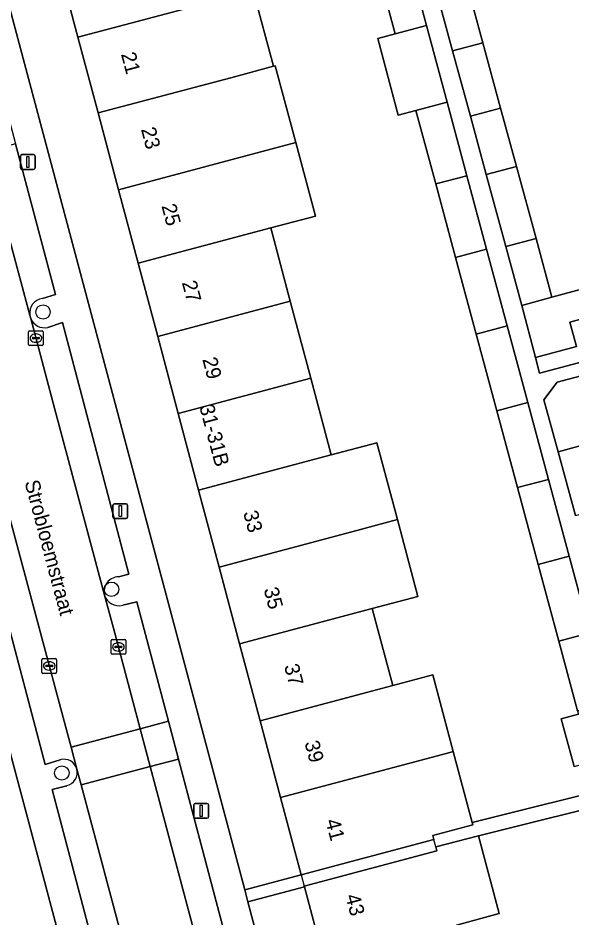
# Model space of a CAD drawing. Extents: x 162542 to 163147, y 380779 to 381521.
# Drawn here: x 162765.3 to 162802.8, y 380919.2 to 380980.2 of the extents above; entities that cross this region are included whole.
import ezdxf

# ---------------------------------------------------------------- set-up
doc = ezdxf.new("R2010")
doc.units = 0
for name, color, linetype in [('IMGEO_Boom', 7, 'Continuous'), ('IMGEO_Erf', 7, 'Continuous'), ('IMGEO_Kolk', 7, 'Continuous'), ('IMGEO_Lichtmast', 7, 'Continuous'), ('IMGEO_Openbare_ruimte_label', 7, 'Continuous'), ('IMGEO_Pand', 7, 'Continuous'), ('IMGEO_Pand_nummerreeks', 7, 'Continuous'), ('IMGEO_Pand_overbouw', 7, 'Continuous'), ('IMGEO_Parkeervlak_open', 7, 'Continuous'), ('IMGEO_Rijbaan_lokaal_open', 7, 'Continuous'), ('IMGEO_Voetpad_open', 7, 'Continuous')]:
    doc.layers.add(name, color=color, linetype=linetype)

msp = doc.modelspace()

# ---------------------------------------------------------------- linework, layer by layer
at = {"layer": 'IMGEO_Boom'}
for centre in [(162766.947, 380960.27), (162771.589, 380941.474), (162768.223, 380929.016)]:
    msp.add_circle(centre, 0.489, dxfattribs=at)
at = {"layer": 'IMGEO_Erf'}
for points in [[(162776.104, 380953.39), (162774.717, 380958.599), (162773.391, 380963.577), (162772.064, 380968.558), (162770.678, 380973.763), (162769.31, 380978.899), (162767.898, 380984.203), (162767.79, 380984.608), (162763.955, 380983.585), (162780.617, 380921.086), (162784.437, 380922.105), (162783.04, 380927.349), (162781.653, 380932.556), (162780.266, 380937.765), (162778.879, 380942.973), (162777.492, 380948.181)], [(162751.467, 380980.135), (162747.619, 380979.111), (162747.702, 380978.798), (162749.067, 380973.666), (162750.432, 380968.535), (162751.797, 380963.403), (162753.162, 380958.272), (162754.527, 380953.141), (162755.892, 380948.009), (162757.257, 380942.877), (162758.623, 380937.745), (162759.988, 380932.613), (162761.352, 380927.483), (162762.717, 380922.351), (162764.079, 380917.227), (162767.943, 380918.262)], [(162787.389, 380911.023), (162785.994, 380916.261), (162784.652, 380921.296), (162780.832, 380920.278), (162787.754, 380894.316), (162788.858, 380889.82), (162787.979, 380889.585), (162787.726, 380889.027), (162790.444, 380878.831), (162792.701, 380879.433), (162791.368, 380884.436), (162789.872, 380890.054), (162791.407, 380890.462), (162790.439, 380894.095), (162791.801, 380894.457), (162791.485, 380895.645), (162790.126, 380900.745), (162788.743, 380905.938)]]:
    msp.add_lwpolyline(points, close=True, dxfattribs=at)
for points in [[(162803.166, 380933.225), (162801.894, 380937.951), (162800.493, 380943.157), (162799.092, 380948.361), (162797.692, 380953.565), (162796.291, 380958.771), (162794.89, 380963.976), (162793.551, 380968.951), (162792.211, 380973.928), (162791.013, 380973.608), (162789.626, 380978.814), (162790.811, 380979.13), (162789.431, 380984.26)], [(162795.55, 380982.944), (162796.75, 380978.521), (162797.95, 380974.098), (162799.023, 380970.143), (162800.35, 380965.253), (162801.428, 380961.277), (162804.268, 380962.047)], [(162781.192, 380982.065), (162782.56, 380976.93), (162782.685, 380976.963), (162784.072, 380971.758), (162785.399, 380966.777), (162782.376, 380965.972), (162783.702, 380960.994), (162785.089, 380955.785), (162786.477, 380950.576), (162789.569, 380951.4), (162790.956, 380946.192), (162792.343, 380940.984), (162789.251, 380940.16), (162790.638, 380934.951), (162793.348, 380935.673), (162794.735, 380930.466), (162796.013, 380925.666), (162806.622, 380928.295)], [(162808.637, 380961.215), (162802.639, 380959.589), (162803.085, 380957.942), (162800.308, 380957.189), (162800.588, 380956.117), (162814.194, 380959.734)], [(162802.928, 380929.454), (162802.058, 380932.686), (162803.227, 380933)], [(162806.857, 380927.348), (162796.44, 380924.766), (162797.847, 380919.483), (162794.967, 380918.7), (162796.43, 380913.206), (162797.685, 380908.496), (162799.067, 380903.307), (162800.42, 380898.227), (162801.843, 380892.883), (162801.926, 380892.571), (162803.223, 380887.695), (162800.276, 380886.911), (162800.948, 380884.389), (162801.506, 380882.293), (162801.634, 380881.813), (162815.673, 380885.555)]]:
    msp.add_lwpolyline(points, dxfattribs=at)
at = {"layer": 'IMGEO_Kolk'}
for p, q in [((162765.967, 380958.074), (162765.967, 380958.926)), ((162766.042, 380959), (162766.894, 380959)), ((162766.455, 380958.78), (162766.48, 380958.78)), ((162766.968, 380958.926), (162766.968, 380958.074)), ((162766.226, 380958.494), (162766.226, 380958.506)), ((162766.664, 380958.457), (162766.266, 380958.457)), ((162766.269, 380958.543), (162766.667, 380958.543)), ((162766.478, 380958.22), (162766.453, 380958.22)), ((162766.71, 380958.506), (162766.71, 380958.494)), ((162766.894, 380958), (162766.042, 380958)), ((162771.629, 380938.062), (162772.481, 380938.062)), ((162771.554, 380937.136), (162771.554, 380937.988)), ((162771.813, 380937.556), (162771.813, 380937.568)), ((162772.251, 380937.519), (162771.853, 380937.519)), ((162771.856, 380937.605), (162772.254, 380937.605)), ((162772.042, 380937.842), (162772.067, 380937.842)), ((162772.297, 380937.568), (162772.297, 380937.556)), ((162772.555, 380937.988), (162772.555, 380937.136)), ((162772.481, 380937.062), (162771.629, 380937.062)), ((162772.065, 380937.282), (162772.04, 380937.282)), ((162766.869, 380935.846), (162766.869, 380936.698)), ((162766.944, 380936.772), (162767.796, 380936.772)), ((162767.128, 380936.266), (162767.128, 380936.278)), ((162767.566, 380936.229), (162767.168, 380936.229)), ((162767.171, 380936.315), (162767.569, 380936.315)), ((162767.357, 380936.552), (162767.382, 380936.552)), ((162767.612, 380936.278), (162767.612, 380936.266)), ((162767.87, 380936.698), (162767.87, 380935.846)), ((162767.796, 380935.772), (162766.944, 380935.772)), ((162767.38, 380935.992), (162767.355, 380935.992))]:
    msp.add_line(p, q, dxfattribs=at)
for points in [[(162765.967, 380958.074), (162765.967, 380958.926)], [(162766.042, 380959), (162766.894, 380959)], [(162766.968, 380958.926), (162766.968, 380958.074)], [(162766.894, 380958), (162766.042, 380958)], [(162771.629, 380938.062), (162772.481, 380938.062)], [(162771.554, 380937.136), (162771.554, 380937.988)], [(162772.555, 380937.988), (162772.555, 380937.136)], [(162772.481, 380937.062), (162771.629, 380937.062)], [(162766.869, 380935.846), (162766.869, 380936.698)], [(162766.944, 380936.772), (162767.796, 380936.772)], [(162767.87, 380936.698), (162767.87, 380935.846)], [(162767.796, 380935.772), (162766.944, 380935.772)]]:
    msp.add_lwpolyline(points, dxfattribs=at)
for centre, radius, start, end in [((162766.044, 380958.924), 0.0765, 91.55205, 178.44795), ((162766.044, 380958.924), 0.0765, 91.55205, 178.44795), ((162766.892, 380958.924), 0.0765, 1.55205, 88.44795), ((162766.892, 380958.924), 0.0765, 1.55205, 88.44795), ((162766.266, 380958.503), 0.0403, 85.87752, 175.75265), ((162766.263, 380958.493), 0.0366, 178.93798, 274.71019), ((162766.667, 380958.5), 0.043, 264.86636, 352.45326), ((162766.671, 380958.505), 0.0386, 1.73085, 96.63898), ((162766.044, 380958.076), 0.0765, 181.55205, 268.44795), ((162766.044, 380958.076), 0.0765, 181.55205, 268.44795), ((162766.892, 380958.076), 0.0765, 271.55205, 358.44795), ((162766.892, 380958.076), 0.0765, 271.55205, 358.44795), ((162771.631, 380937.986), 0.0765, 91.55205, 178.44795), ((162771.631, 380937.986), 0.0765, 91.55205, 178.44795), ((162772.479, 380937.986), 0.0765, 1.55205, 88.44795), ((162772.479, 380937.986), 0.0765, 1.55205, 88.44795), ((162771.853, 380937.565), 0.0403, 85.87752, 175.75265), ((162771.85, 380937.555), 0.0366, 178.93798, 274.71019), ((162772.254, 380937.562), 0.043, 264.86636, 352.45326), ((162772.258, 380937.567), 0.0386, 1.73085, 96.63898), ((162771.631, 380937.138), 0.0765, 181.55205, 268.44795), ((162771.631, 380937.138), 0.0765, 181.55205, 268.44795), ((162772.479, 380937.138), 0.0765, 271.55205, 358.44795), ((162772.479, 380937.138), 0.0765, 271.55205, 358.44795), ((162766.946, 380936.696), 0.0765, 91.55205, 178.44795), ((162766.946, 380936.696), 0.0765, 91.55205, 178.44795), ((162767.168, 380936.275), 0.0403, 85.87752, 175.75265), ((162767.165, 380936.265), 0.0366, 178.93798, 274.71019), ((162767.569, 380936.272), 0.043, 264.86636, 352.45326), ((162767.573, 380936.277), 0.0386, 1.73085, 96.63898), ((162767.794, 380936.696), 0.0765, 1.55205, 88.44795), ((162767.794, 380936.696), 0.0765, 1.55205, 88.44795), ((162766.946, 380935.848), 0.0765, 181.55205, 268.44795), ((162766.946, 380935.848), 0.0765, 181.55205, 268.44795), ((162767.794, 380935.848), 0.0765, 271.55205, 358.44795), ((162767.794, 380935.848), 0.0765, 271.55205, 358.44795)]:
    msp.add_arc(centre, radius, start, end, dxfattribs=at)
for centre, major_axis, ratio, start_param, end_param in [((162766.454, 380958.5), (-0.387, 0.002), 0.722429, 4.712389, 7.853982), ((162766.479, 380958.5), (-0.39, 0.002), 0.717154, 1.570796, 4.712389), ((162772.041, 380937.562), (-0.387, 0.002), 0.722429, 4.712389, 7.853982), ((162772.066, 380937.562), (-0.39, 0.002), 0.717154, 1.570796, 4.712389), ((162767.356, 380936.272), (-0.387, 0.002), 0.722429, 4.712389, 7.853982), ((162767.381, 380936.272), (-0.39, 0.002), 0.717154, 1.570796, 4.712389)]:
    msp.add_ellipse(centre, major_axis=major_axis, ratio=ratio, start_param=start_param, end_param=end_param, dxfattribs=at)
at = {"layer": 'IMGEO_Lichtmast'}
for p, q in [((162765.423, 380970.042), (162765.423, 380970.842)), ((162765.423, 380970.842), (162765.423, 380970.042)), ((162765.523, 380970.942), (162766.313, 380970.942)), ((162766.313, 380970.942), (162765.523, 380970.942)), ((162766.413, 380970.842), (162766.413, 380970.042)), ((162766.413, 380970.042), (162766.413, 380970.842)), ((162766.313, 380969.942), (162765.523, 380969.942)), ((162765.523, 380969.942), (162766.313, 380969.942)), ((162771.787, 380947.27), (162772.577, 380947.27)), ((162772.577, 380947.27), (162771.787, 380947.27)), ((162771.687, 380946.37), (162771.687, 380947.17)), ((162771.687, 380947.17), (162771.687, 380946.37)), ((162772.677, 380947.17), (162772.677, 380946.37)), ((162772.677, 380946.37), (162772.677, 380947.17)), ((162772.577, 380946.27), (162771.787, 380946.27)), ((162771.787, 380946.27), (162772.577, 380946.27)), ((162777.166, 380926.051), (162777.166, 380926.851)), ((162777.166, 380926.851), (162777.166, 380926.051)), ((162777.266, 380926.951), (162778.056, 380926.951)), ((162778.056, 380926.951), (162777.266, 380926.951)), ((162778.156, 380926.851), (162778.156, 380926.051)), ((162778.156, 380926.051), (162778.156, 380926.851)), ((162778.056, 380925.951), (162777.266, 380925.951)), ((162777.266, 380925.951), (162778.056, 380925.951))]:
    msp.add_line(p, q, dxfattribs=at)
for points in [[(162765.843, 380970.817), (162765.993, 380970.817), (162765.993, 380970.067), (162765.843, 380970.067), (162765.843, 380970.817)], [(162772.107, 380947.145), (162772.257, 380947.145), (162772.257, 380946.395), (162772.107, 380946.395), (162772.107, 380947.145)], [(162777.586, 380926.826), (162777.736, 380926.826), (162777.736, 380926.076), (162777.586, 380926.076), (162777.586, 380926.826)]]:
    msp.add_lwpolyline(points, dxfattribs=at)
for centre, start, end in [((162765.523, 380970.842), 90, 180), ((162765.523, 380970.842), 90, 180), ((162766.313, 380970.842), 0, 90), ((162766.313, 380970.842), 360, 90), ((162765.523, 380970.042), 180, 270), ((162765.523, 380970.042), 180, 270), ((162766.313, 380970.042), 270, 0), ((162766.313, 380970.042), 270, 0), ((162771.787, 380947.17), 90, 180), ((162771.787, 380947.17), 90, 180), ((162772.577, 380947.17), 0, 90), ((162772.577, 380947.17), 360, 90), ((162771.787, 380946.37), 180, 270), ((162771.787, 380946.37), 180, 270), ((162772.577, 380946.37), 270, 0), ((162772.577, 380946.37), 270, 0), ((162777.266, 380926.851), 90, 180), ((162777.266, 380926.851), 90, 180), ((162778.056, 380926.851), 0, 90), ((162778.056, 380926.851), 360, 90), ((162777.266, 380926.051), 180, 270), ((162777.266, 380926.051), 180, 270), ((162778.056, 380926.051), 270, 0), ((162778.056, 380926.051), 270, 0)]:
    msp.add_arc(centre, 0.1, start, end, dxfattribs=at)
at = {"layer": 'IMGEO_Pand'}
for points in [[(162779.767, 380987.412), (162779.654, 380987.837), (162776.758, 380987.065), (162776.416, 380986.974), (162776.539, 380986.511), (162771.439, 380985.144), (162767.898, 380984.203), (162769.31, 380978.899), (162781.192, 380982.065)], [(162789.431, 380984.26), (162790.811, 380979.13), (162792.92, 380979.692), (162791.54, 380984.822)], [(162795.55, 380982.944), (162793.499, 380982.396), (162794.699, 380977.973), (162796.75, 380978.521)], [(162781.192, 380982.065), (162769.31, 380978.899), (162770.678, 380973.763), (162779.663, 380976.158), (162782.56, 380976.93)], [(162792.92, 380979.692), (162790.811, 380979.13), (162789.626, 380978.814), (162791.013, 380973.608), (162792.211, 380973.928), (162794.318, 380974.49)], [(162796.75, 380978.521), (162794.699, 380977.973), (162795.899, 380973.55), (162797.95, 380974.098)], [(162782.685, 380976.963), (162782.56, 380976.93), (162779.663, 380976.158), (162770.678, 380973.763), (162772.064, 380968.558), (162784.072, 380971.758)], [(162792.211, 380973.928), (162793.551, 380968.951), (162795.657, 380969.512), (162794.318, 380974.49)], [(162797.95, 380974.098), (162795.899, 380973.55), (162796.974, 380969.587), (162799.023, 380970.143)], [(162782.376, 380965.972), (162785.399, 380966.777), (162784.072, 380971.758), (162772.064, 380968.558), (162773.391, 380963.577)], [(162799.023, 380970.143), (162796.974, 380969.587), (162798.299, 380964.704), (162800.35, 380965.253)], [(162794.89, 380963.976), (162796.994, 380964.537), (162795.657, 380969.512), (162793.551, 380968.951)], [(162774.717, 380958.599), (162783.702, 380960.994), (162782.376, 380965.972), (162773.391, 380963.577)], [(162800.35, 380965.253), (162798.299, 380964.704), (162799.38, 380960.722), (162801.428, 380961.277)], [(162796.994, 380964.537), (162794.89, 380963.976), (162796.291, 380958.771), (162798.394, 380959.331)], [(162808.637, 380961.215), (162808.128, 380963.094), (162804.268, 380962.047), (162801.428, 380961.277), (162799.38, 380960.722), (162800.308, 380957.189), (162803.085, 380957.942), (162802.639, 380959.589)], [(162774.717, 380958.599), (162776.104, 380953.39), (162785.089, 380955.785), (162783.702, 380960.994)], [(162797.692, 380953.565), (162799.794, 380954.126), (162798.394, 380959.331), (162796.291, 380958.771)], [(162805.701, 380956.553), (162801.771, 380955.512), (162800.881, 380954.316), (162801.843, 380950.786), (162806.711, 380952.113), (162806.876, 380952.157)], [(162785.089, 380955.785), (162776.104, 380953.39), (162777.492, 380948.181), (162786.477, 380950.576)], [(162801.193, 380948.921), (162799.794, 380954.126), (162797.692, 380953.565), (162799.092, 380948.361)], [(162806.711, 380952.113), (162801.843, 380950.786), (162803.02, 380946.469), (162807.872, 380947.765)], [(162786.477, 380950.576), (162777.492, 380948.181), (162778.879, 380942.973), (162787.864, 380945.368), (162790.956, 380946.192), (162789.569, 380951.4)], [(162801.193, 380948.921), (162799.092, 380948.361), (162800.493, 380943.157), (162802.592, 380943.716)], [(162787.864, 380945.368), (162778.879, 380942.973), (162780.266, 380937.765), (162789.251, 380940.16), (162792.343, 380940.984), (162790.956, 380946.192)], [(162801.894, 380937.951), (162803.992, 380938.511), (162802.592, 380943.716), (162800.493, 380943.157)], [(162780.266, 380937.765), (162781.653, 380932.556), (162790.638, 380934.951), (162789.251, 380940.16)], [(162801.894, 380937.951), (162803.166, 380933.225), (162805.261, 380933.789), (162803.992, 380938.511)], [(162793.348, 380935.673), (162790.638, 380934.951), (162781.653, 380932.556), (162783.04, 380927.349), (162794.354, 380930.365), (162794.735, 380930.466)], [(162805.261, 380933.789), (162803.166, 380933.225), (162803.227, 380933), (162802.058, 380932.686), (162802.928, 380929.454), (162806.122, 380930.314)], [(162796.013, 380925.666), (162794.735, 380930.466), (162794.354, 380930.365), (162783.04, 380927.349), (162784.437, 380922.105), (162793.422, 380924.5), (162793.35, 380924.768), (162796.06, 380925.49)], [(162796.44, 380924.766), (162793.556, 380923.998), (162793.626, 380923.737), (162784.64, 380921.342), (162784.652, 380921.296), (162785.994, 380916.261), (162794.967, 380918.7), (162797.847, 380919.483)]]:
    msp.add_lwpolyline(points, close=True, dxfattribs=at)
at = {"layer": 'IMGEO_Pand_overbouw'}
msp.add_lwpolyline([(162793.626, 380923.737), (162793.556, 380923.998), (162793.422, 380924.5), (162784.437, 380922.105), (162784.64, 380921.342)], close=True, dxfattribs=at)
at = {"layer": 'IMGEO_Parkeervlak_open'}
for points in [[(162766.904, 380961.192), (162767.792, 380961.461), (162765.084, 380971.665), (162763.108, 380971.14), (162764.244, 380966.819), (162766.059, 380960.054)], [(162766.115, 380959.838), (162767.646, 380954.085), (162771.115, 380941.082)], [(162772.068, 380942.321), (162772.766, 380942.488), (162768.266, 380959.557), (162767.263, 380959.225)], [(162769.244, 380929.276), (162768.845, 380930.769), (162768.149, 380933.373), (162764.006, 380948.824), (162763.748, 380949.807)], [(162763.22, 380948.728), (162762.116, 380948.396), (162767.103, 380929.588), (162768.105, 380929.907)], [(162771.115, 380941.082), (162771.712, 380938.843), (162773.532, 380932.015), (162775.443, 380932.523), (162773.303, 380940.622), (162772.351, 380940.392)], [(162779.19, 380915.442), (162779.888, 380915.697), (162776.12, 380929.96), (162774.215, 380929.454), (162778.249, 380914.26)], [(162776.334, 380902.519), (162772.635, 380916.59), (162769.53, 380928.208), (162769.244, 380929.276)], [(162768.553, 380928.156), (162767.576, 380927.887), (162774.135, 380902.949), (162775.099, 380903.218)]]:
    msp.add_lwpolyline(points, dxfattribs=at)
msp.add_lwpolyline([(162773.532, 380932.015), (162774.215, 380929.454), (162776.12, 380929.96), (162775.443, 380932.523)], close=True, dxfattribs=at)
for centre, radius, start, end in [((162767.051, 380960.2), 1.003, 98.42619, 188.38377), ((162767.044, 380960.196), 0.996, 201.09376, 282.7043), ((162772.09, 380941.318), 1.003, 91.24888, 193.61841), ((162772.085, 380941.368), 1.012, 196.43774, 285.21717), ((162768.368, 380929.038), 0.908, 15.20595, 106.8216), ((162768.341, 380929.06), 0.928, 283.18918, 13.46461)]:
    msp.add_arc(centre, radius, start, end, dxfattribs=at)
at = {"layer": 'IMGEO_Rijbaan_lokaal_open'}
for points in [[(162766.059, 380960.054), (162764.244, 380966.819), (162763.108, 380971.14), (162758.458, 380969.904), (162763.748, 380949.807), (162764.006, 380948.824), (162768.149, 380933.373), (162768.845, 380930.769), (162773.532, 380932.015), (162771.712, 380938.843), (162771.115, 380941.082), (162767.646, 380954.085), (162766.115, 380959.838)], [(162768.845, 380930.769), (162769.244, 380929.276), (162769.53, 380928.208), (162774.215, 380929.454), (162773.532, 380932.015)], [(162778.29, 380914.105), (162778.249, 380914.26), (162774.215, 380929.454), (162769.53, 380928.208), (162772.635, 380916.59), (162776.334, 380902.519), (162776.409, 380902.238), (162780.272, 380887.798), (162785.006, 380889.053), (162784.888, 380889.476), (162784.223, 380891.867), (162780.844, 380904.471)]]:
    msp.add_lwpolyline(points, close=True, dxfattribs=at)
at = {"layer": 'IMGEO_Voetpad_open'}
for points in [[(162784.888, 380889.476), (162785.006, 380889.053), (162785.664, 380886.45), (162788.238, 380876.778), (162790.799, 380877.498), (162790.444, 380878.831), (162787.726, 380889.027), (162787.979, 380889.585), (162788.858, 380889.82), (162787.754, 380894.316), (162780.832, 380920.278), (162780.617, 380921.086), (162763.955, 380983.585), (162763.686, 380984.593), (162759.578, 381000), (162755.726, 381014.447), (162754.046, 381014.881), (162751.366, 381025.19), (162751.014, 381026.543), (162750.404, 381028.836), (162749.506, 381032.166), (162746.399, 381043.845)], [(162739.036, 381041.753), (162736.762, 381041.139), (162739.873, 381029.488), (162740.737, 381026.252), (162741.338, 381024.003), (162741.713, 381022.565), (162744.463, 381012.029), (162743.026, 381011.614), (162746.28, 381000), (162748.205, 380992.388), (162751.174, 380981.237), (162751.467, 380980.135), (162767.943, 380918.262), (162768.14, 380917.522), (162776.41, 380886.464), (162777.36, 380886.698), (162778.067, 380886.244), (162780.774, 380876.082), (162781.077, 380874.945), (162783.57, 380875.561), (162782.851, 380878.347), (162780.982, 380885.195), (162780.272, 380887.798)], [(162814.194, 380959.734), (162800.588, 380956.117), (162800.308, 380957.189), (162799.38, 380960.722), (162798.299, 380964.704), (162796.974, 380969.587), (162795.899, 380973.55), (162794.699, 380977.973), (162793.499, 380982.396), (162792.299, 380986.818), (162791.102, 380991.227), (162789.849, 380990.887), (162789.607, 380990.821), (162788.31, 380995.603), (162788.158, 380996.163), (162789.438, 380996.499), (162788.985, 380998.327), (162788.195, 381001.514), (162787.205, 381005.213), (162786.299, 381008.2), (162785.313, 381011.883), (162783.948, 381016.982), (162783.558, 381018.525), (162782.552, 381022.284)], [(162791.54, 380984.822), (162792.92, 380979.692), (162794.318, 380974.49), (162795.657, 380969.512), (162796.994, 380964.537), (162798.394, 380959.331), (162799.794, 380954.126), (162801.193, 380948.921), (162802.592, 380943.716), (162803.992, 380938.511)], [(162761.343, 380981.752), (162762.333, 380982.033), (162764.42, 380974.169), (162765.084, 380971.665), (162767.792, 380961.461), (162766.904, 380961.192)], [(162766.059, 380960.054), (162766.115, 380959.838)], [(162767.263, 380959.225), (162768.266, 380959.557), (162772.766, 380942.488), (162772.068, 380942.321)], [(162803.02, 380946.469), (162801.843, 380950.786), (162800.881, 380954.316), (162801.771, 380955.512), (162805.701, 380956.553)], [(162768.105, 380929.907), (162767.103, 380929.588), (162762.116, 380948.396), (162763.22, 380948.728)], [(162772.351, 380940.392), (162773.303, 380940.622), (162775.443, 380932.523), (162776.12, 380929.96), (162779.888, 380915.697), (162779.19, 380915.442)], [(162806.622, 380928.295), (162796.013, 380925.666), (162796.06, 380925.49), (162793.35, 380924.768), (162793.422, 380924.5), (162784.437, 380922.105), (162780.617, 380921.086), (162780.832, 380920.278), (162784.652, 380921.296), (162784.64, 380921.342), (162793.626, 380923.737), (162793.556, 380923.998), (162796.44, 380924.766), (162806.857, 380927.348)], [(162775.099, 380903.218), (162774.135, 380902.949), (162767.576, 380927.887), (162768.553, 380928.156)]]:
    msp.add_lwpolyline(points, dxfattribs=at)
for centre, radius, start, end in [((162767.051, 380960.2), 1.003, 98.42619, 188.38377), ((162767.044, 380960.196), 0.996, 201.09376, 282.7043), ((162772.09, 380941.318), 1.003, 91.24888, 193.61841), ((162772.085, 380941.368), 1.012, 196.43774, 285.21717), ((162768.368, 380929.038), 0.908, 15.20595, 106.8216), ((162768.341, 380929.06), 0.928, 283.18918, 13.46461)]:
    msp.add_arc(centre, radius, start, end, dxfattribs=at)

# ---------------------------------------------------------------- texts
at = {"layer": 'IMGEO_Openbare_ruimte_label'}
msp.add_text('Strobloemstraat', height=1, rotation=284.95356, dxfattribs=at).set_placement((162765.689, 380948.74))
at = {"layer": 'IMGEO_Pand_nummerreeks'}
for s, rotation, p in [('21', 284.91388, (162772.223, 380977.753)), ('23', 284.91388, (162773.578, 380972.663)), ('25', 284.91429, (162774.964, 380967.465)), ('27', 284.91429, (162776.348, 380962.266)), ('29', 284.91429, (162777.733, 380957.067)), ('31-31B', 284.91961, (162777.528, 380953.87)), ('33', 284.91388, (162780.501, 380946.67)), ('35', 284.91429, (162781.887, 380941.471)), ('37', 284.91429, (162783.271, 380936.273)), ('39', 284.91388, (162784.655, 380931.074)), ('41', 284.91388, (162786.07, 380925.767)), ('43', 284.91388, (162787.424, 380920.677))]:
    msp.add_text(s, height=1, rotation=rotation, dxfattribs=at).set_placement(p)

doc.saveas('drawing.dxf')
